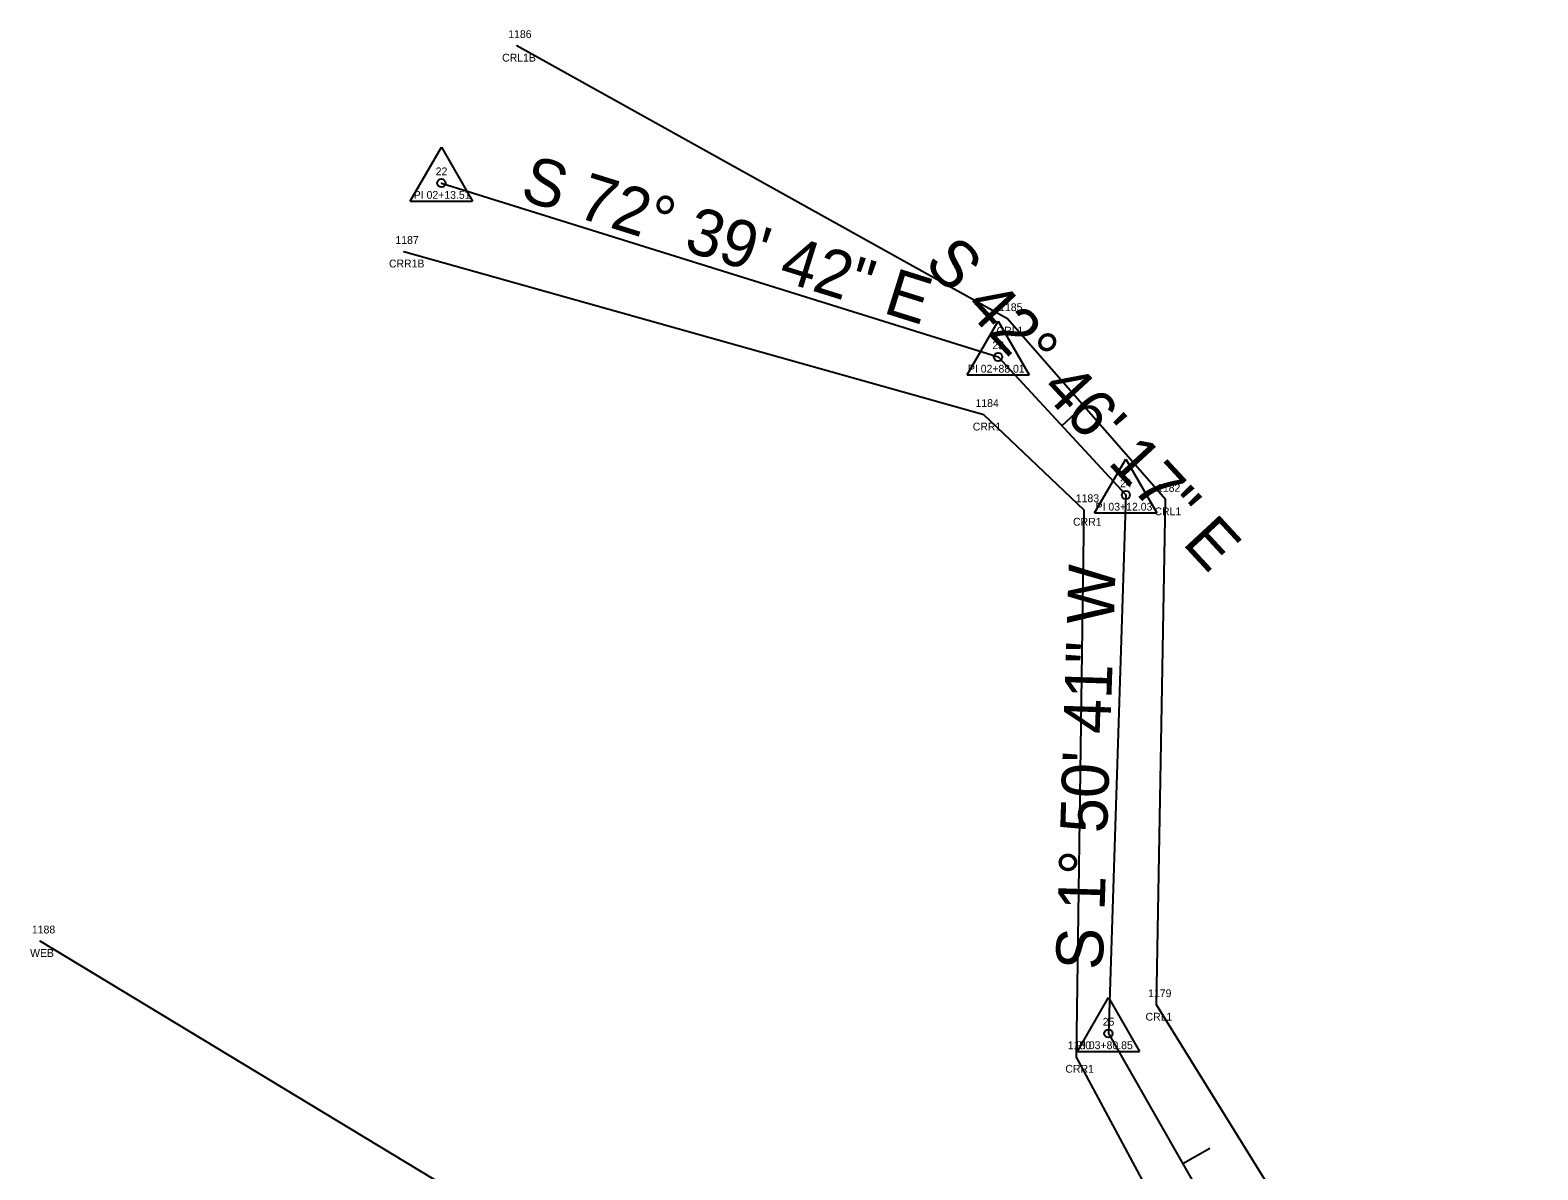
# Model space of a CAD drawing. Extents: x 2445178 to 2446205, y 790762 to 792372.
# Drawn here: x 2445202.9 to 2445395.5, y 792045.3 to 792190.9 of the extents above; entities that cross this region are included whole.
import ezdxf

# ---------------------------------------------------------------- set-up
doc = ezdxf.new("R2010")
doc.units = 0
for name, color, linetype in [('RD_EX_H2O', 7, 'Continuous'), ('RD_EX_H2O_txCode', 7, 'Continuous'), ('RD_HC_Cl', 7, 'Continuous'), ('RD_HC_Data', 7, 'Continuous'), ('RD_HC_Data_Tic', 7, 'Continuous'), ('RD_HC_txCode', 7, 'Continuous'), ('RD_SMD_Locator', 7, 'Continuous')]:
    doc.layers.add(name, color=color, linetype=linetype)

msp = doc.modelspace()

# ---------------------------------------------------------------- linework, layer by layer
at = {"layer": 'RD_EX_H2O'}
for points in [[(2445415.21, 791826.15), (2445411.13, 791915.36), (2445401.26, 791978.48), (2445346.75, 792066.4), (2445347.89, 792130.96), (2445327.72, 792154.04), (2445265.04, 792188.92)], [(2445403.09, 791820.76), (2445401.57, 791912.69), (2445385.3, 791968.86), (2445336.54, 792059.75), (2445337.52, 792129.63), (2445324.7, 792141.79), (2445250.6, 792162.62)], [(2445390.88, 791910.3), (2445375.84, 791957.27), (2445276.8, 792030.59), (2445204.16, 792074.54)]]:
    msp.add_lwpolyline(points, dxfattribs=at)
at = {"layer": 'RD_HC_Cl'}
for p, q in [((2445255.41, 792171.39), (2445326.53, 792149.18)), ((2445326.53, 792149.18), (2445342.84, 792131.55)), ((2445342.84, 792131.55), (2445340.62, 792062.76)), ((2445340.62, 792062.76), (2445391.36, 791973.89))]:
    msp.add_line(p, q, dxfattribs=at)
at = {"layer": 'RD_HC_Data'}
for p, q in [((2445251.44, 792169.09), (2445255.41, 792175.97)), ((2445255.41, 792175.97), (2445259.38, 792169.09)), ((2445251.44, 792169.09), (2445259.38, 792169.09)), ((2445322.56, 792146.89), (2445326.53, 792153.77)), ((2445326.53, 792153.77), (2445330.5, 792146.89)), ((2445322.56, 792146.89), (2445330.5, 792146.89)), ((2445338.86, 792129.26), (2445342.84, 792136.14)), ((2445342.84, 792136.14), (2445346.81, 792129.26)), ((2445338.86, 792129.26), (2445346.81, 792129.26)), ((2445336.65, 792060.47), (2445340.62, 792067.35)), ((2445340.62, 792067.35), (2445344.59, 792060.47)), ((2445336.65, 792060.47), (2445344.59, 792060.47))]:
    msp.add_line(p, q, dxfattribs=at)
for centre in [(2445255.41, 792171.39), (2445326.53, 792149.18), (2445342.84, 792131.55), (2445340.62, 792062.76)]:
    msp.add_circle(centre, 0.529, dxfattribs=at)
at = {"layer": 'RD_HC_Data_Tic'}
for p, q in [((2445334.67, 792140.38), (2445337.61, 792143.1)), ((2445350.11, 792046.13), (2445353.59, 792048.12))]:
    msp.add_line(p, q, dxfattribs=at)
at = {"layer": 'RD_SMD_Locator'}
for centre in [(2445265.04, 792188.92), (2445255.41, 792171.39), (2445250.6, 792162.62), (2445327.72, 792154.04), (2445326.53, 792149.18), (2445324.7, 792141.79), (2445342.84, 792131.55), (2445347.89, 792130.96), (2445337.52, 792129.63), (2445204.16, 792074.54), (2445346.75, 792066.4), (2445340.62, 792062.76), (2445336.54, 792059.75)]:
    msp.add_circle(centre, 0.001, dxfattribs=at)

# ---------------------------------------------------------------- texts
at = {"layer": 'RD_EX_H2O_txCode'}
for s, p in [('1186', (2445263.95, 792189.92)), ('CRL1B', (2445263.17, 792186.92)), ('1187', (2445249.54, 792163.62)), ('CRR1B', (2445248.71, 792160.62)), ('1185', (2445326.66, 792155.04)), ('CRL1', (2445326.33, 792152.04)), ('1184', (2445323.64, 792142.79)), ('CRR1', (2445323.29, 792139.79)), ('1182', (2445346.83, 792131.96)), ('1183', (2445336.45, 792130.63)), ('CRR1', (2445336.1, 792127.63)), ('CRL1', (2445346.5, 792128.96)), ('1188', (2445203.1, 792075.54)), ('WEB', (2445202.87, 792072.54)), ('1179', (2445345.69, 792067.4)), ('CRL1', (2445345.36, 792064.4)), ('1180', (2445335.43, 792060.75)), ('CRR1', (2445335.12, 792057.75))]:
    msp.add_text(s, height=1, dxfattribs=at).set_placement(p)
at = {"layer": 'RD_HC_Data'}
for s, rotation, p in [('S 72%%d 39\' 42" E', 342.6618, (2445265.26, 792169.36)), ('S 42%%d 46\' 17" E', 312.7715, (2445316.92, 792161.05)), ('S 1%%d 50\' 41" W', 88.1552, (2445339.88, 792070.82))]:
    msp.add_text(s, height=6, rotation=rotation, dxfattribs=at).set_placement(p)
at = {"layer": 'RD_HC_txCode'}
for s, p in [('22', (2445254.68, 792172.39)), ('PI 02+13.51', (2445251.88, 792169.39)), ('23', (2445325.79, 792150.18)), ('PI 02+88.01', (2445322.67, 792147.18)), ('24', (2445342.1, 792132.55)), ('PI 03+12.03', (2445338.98, 792129.55)), ('25', (2445339.89, 792063.76)), ('PI 03+80.85', (2445336.48, 792060.76))]:
    msp.add_text(s, height=1, dxfattribs=at).set_placement(p)

doc.saveas('drawing.dxf')
